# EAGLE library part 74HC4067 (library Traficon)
16 channel analog multiplexer/demultiplexer
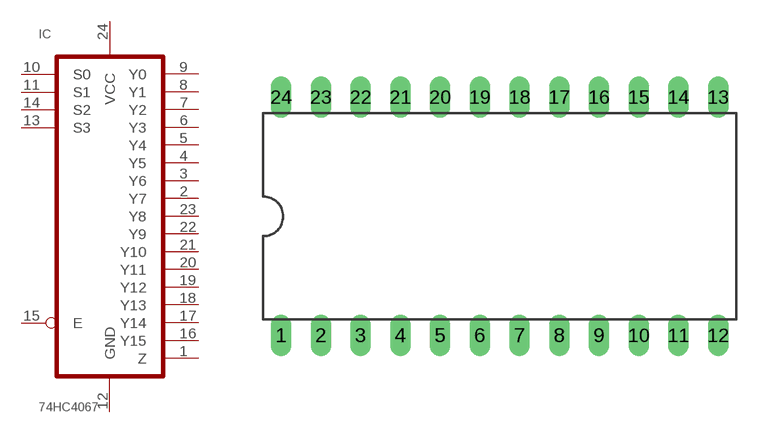
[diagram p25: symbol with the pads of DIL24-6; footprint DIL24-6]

Designator prefix IC

## 74HC4067  [DIL24-6]
1  Z
2  Y7
3  Y6
4  Y5
5  Y4
6  Y3
7  Y2
8  Y1
9  Y0
10  S0  in
11  S1  in
12  GND  pwr
13  S3  in
14  S2  in
15  E  in
16  Y15
17  Y14
18  Y13
19  Y12
20  Y11
21  Y10
22  Y9
23  Y8
24  VCC  pwr

## Footprint DIL24-6 (pad centres in mm)
drill 0.813 long: 1 -12.7,-7.62; 2 -10.16,-7.62; 3 -7.62,-7.62; 4 -5.08,-7.62; 5 -2.54,-7.62; 6 0,-7.62; 7 2.54,-7.62; 8 5.08,-7.62; 9 7.62,-7.62; 10 10.16,-7.62; 11 12.7,-7.62; 12 15.24,-7.62; 13 15.24,7.62; 14 12.7,7.62; 15 10.16,7.62; 16 7.62,7.62; 17 5.08,7.62; 18 2.54,7.62; 19 0,7.62; 20 -2.54,7.62; 21 -5.08,7.62; 22 -7.62,7.62; 23 -10.16,7.62; 24 -12.7,7.62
